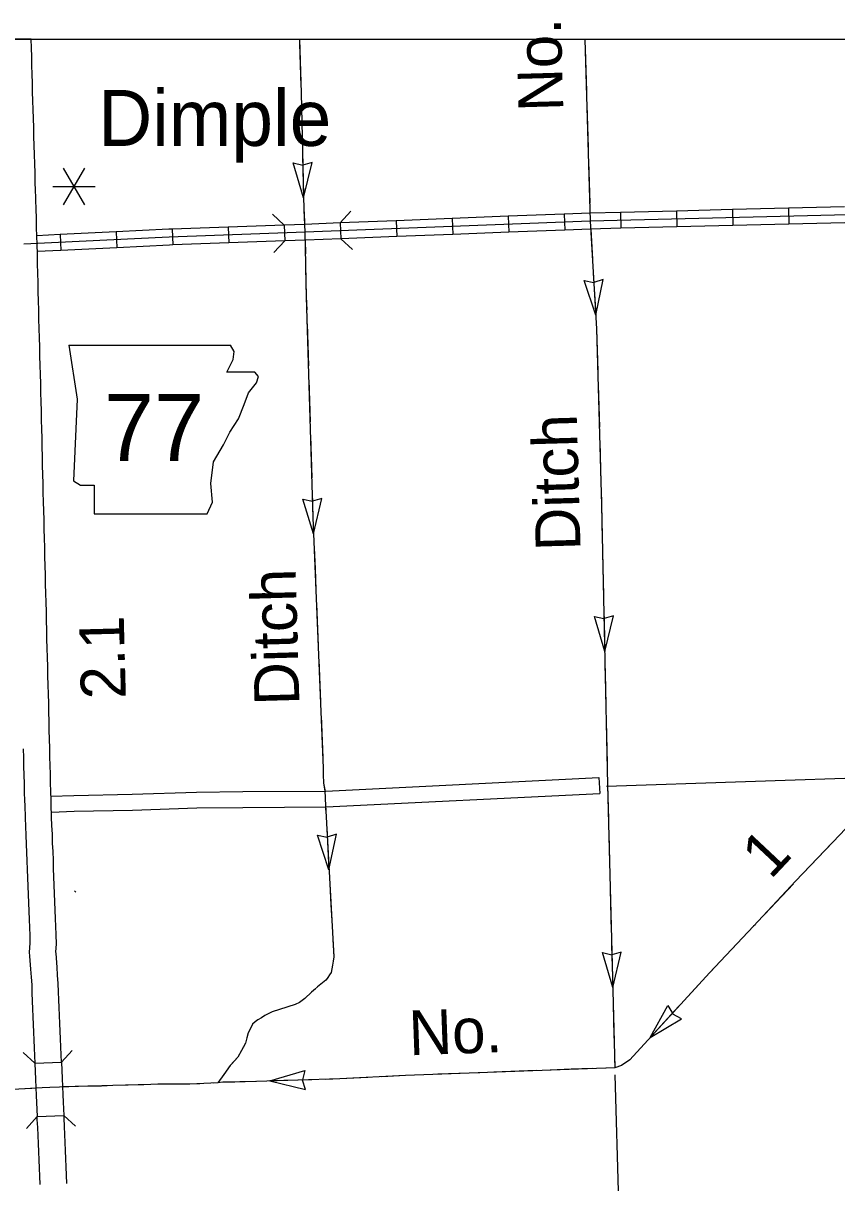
# Model space of a CAD drawing. Extents: x -117616 to 64730, y 54117 to 789866.
# Drawn here: x 63077.4 to 63230.7, y 55099.4 to 55318 of the extents above; entities that cross this region are included whole.
import ezdxf

# ---------------------------------------------------------------- set-up
doc = ezdxf.new("R2010")
doc.units = 0
for name, color, linetype in [('10', 7, 'Continuous'), ('21', 7, 'Continuous'), ('24', 7, 'Continuous'), ('32', 7, 'Continuous'), ('35', 7, 'Continuous'), ('37', 7, 'Continuous'), ('38', 7, 'Continuous'), ('43', 7, 'Continuous'), ('46', 7, 'Continuous'), ('48', 7, 'Continuous'), ('5', 7, 'Continuous'), ('R_No Plot', 7, 'Continuous')]:
    doc.layers.add(name, color=color, linetype=linetype)

msp = doc.modelspace()

# ---------------------------------------------------------------- linework, layer by layer
at = {"layer": '10'}
for p, q in [((63078.91, 55314.94), (63073.89, 55314.94)), ((63079, 55313.33), (63078.91, 55314.94)), ((63079.05, 55311.64), (63079, 55313.33)), ((63079.08, 55309.98), (63079.05, 55311.64)), ((63079.13, 55308.34), (63079.08, 55309.98)), ((63079.17, 55306.68), (63079.13, 55308.34)), ((63079.22, 55305.02), (63079.17, 55306.68)), ((63079.27, 55303.36), (63079.22, 55305.02)), ((63079.32, 55301.69), (63079.27, 55303.36)), ((63079.38, 55300.02), (63079.32, 55301.69)), ((63079.43, 55298.32), (63079.38, 55300.02)), ((63079.47, 55296.61), (63079.43, 55298.32)), ((63079.51, 55294.91), (63079.47, 55296.61)), ((63079.56, 55293.21), (63079.51, 55294.91)), ((63079.61, 55291.5), (63079.56, 55293.21)), ((63079.67, 55289.79), (63079.61, 55291.5)), ((63079.72, 55288.07), (63079.67, 55289.79)), ((63079.77, 55286.36), (63079.72, 55288.07)), ((63079.8, 55285.23), (63079.77, 55286.36)), ((63079.82, 55284.66), (63079.8, 55285.23)), ((63079.87, 55282.96), (63079.82, 55284.66)), ((63079.93, 55281.24), (63079.87, 55282.96)), ((63079.97, 55279.52), (63079.93, 55281.24)), ((63080.01, 55277.8), (63079.97, 55279.52)), ((63080.05, 55276.38), (63080.01, 55277.8)), ((63080.11, 55274.35), (63080.05, 55276.38)), ((63080.15, 55272.62), (63080.11, 55274.35)), ((63080.2, 55270.88), (63080.15, 55272.62)), ((63080.24, 55269.13), (63080.2, 55270.88)), ((63080.28, 55267.38), (63080.24, 55269.13)), ((63080.32, 55265.64), (63080.28, 55267.38)), ((63080.36, 55263.91), (63080.32, 55265.64)), ((63080.41, 55262.17), (63080.36, 55263.91)), ((63080.46, 55260.43), (63080.41, 55262.17)), ((63080.5, 55258.7), (63080.46, 55260.43)), ((63080.55, 55256.98), (63080.5, 55258.7)), ((63080.6, 55255.25), (63080.55, 55256.98)), ((63080.65, 55253.52), (63080.6, 55255.25)), ((63080.69, 55251.8), (63080.65, 55253.52)), ((63080.74, 55250.07), (63080.69, 55251.8)), ((63080.79, 55248.35), (63080.74, 55250.07)), ((63080.83, 55246.63), (63080.79, 55248.35)), ((63080.87, 55244.91), (63080.83, 55246.63)), ((63080.9, 55243.2), (63080.87, 55244.91)), ((63080.95, 55241.49), (63080.9, 55243.2)), ((63080.99, 55239.78), (63080.95, 55241.49)), ((63081.03, 55238.07), (63080.99, 55239.78)), ((63081.07, 55236.36), (63081.03, 55238.07)), ((63081.1, 55234.65), (63081.07, 55236.36)), ((63081.14, 55232.95), (63081.1, 55234.65)), ((63081.19, 55231.24), (63081.14, 55232.95)), ((63081.23, 55229.52), (63081.19, 55231.24)), ((63081.28, 55227.8), (63081.23, 55229.52)), ((63081.32, 55226.08), (63081.28, 55227.8)), ((63081.37, 55224.36), (63081.32, 55226.08)), ((63081.41, 55222.63), (63081.37, 55224.36)), ((63081.45, 55220.9), (63081.41, 55222.63)), ((63081.5, 55219.17), (63081.45, 55220.9)), ((63081.54, 55217.44), (63081.5, 55219.17)), ((63081.58, 55215.71), (63081.54, 55217.44)), ((63081.62, 55213.99), (63081.58, 55215.71)), ((63081.67, 55212.27), (63081.62, 55213.99)), ((63081.72, 55210.54), (63081.67, 55212.27)), ((63081.76, 55208.81), (63081.72, 55210.54)), ((63081.8, 55207.08), (63081.76, 55208.81)), ((63081.84, 55205.36), (63081.8, 55207.08)), ((63081.88, 55203.64), (63081.84, 55205.36)), ((63081.92, 55201.91), (63081.88, 55203.64)), ((63081.97, 55200.19), (63081.92, 55201.91)), ((63082.01, 55198.46), (63081.97, 55200.19)), ((63082.06, 55196.73), (63082.01, 55198.46)), ((63082.11, 55195), (63082.06, 55196.73)), ((63082.15, 55193.28), (63082.11, 55195)), ((63082.2, 55191.56), (63082.15, 55193.28)), ((63082.24, 55189.84), (63082.2, 55191.56)), ((63082.27, 55188.12), (63082.24, 55189.84)), ((63082.31, 55186.42), (63082.27, 55188.12)), ((63082.35, 55184.74), (63082.31, 55186.42)), ((63082.4, 55183.05), (63082.35, 55184.74)), ((63082.44, 55181.37), (63082.4, 55183.05)), ((63077.44, 55181.25), (63077.47, 55179.58)), ((63077.47, 55179.58), (63077.52, 55177.93)), ((63082.47, 55179.7), (63082.44, 55181.37)), ((63082.51, 55178.06), (63082.47, 55179.7)), ((63077.52, 55177.93), (63077.56, 55176.29)), ((63082.56, 55176.43), (63082.51, 55178.06)), ((63077.56, 55176.29), (63077.61, 55174.68)), ((63082.6, 55174.8), (63082.56, 55176.43)), ((63077.61, 55174.68), (63077.64, 55173.07)), ((63077.64, 55173.07), (63077.69, 55171.43)), ((63082.64, 55173.19), (63082.6, 55174.8)), ((63082.68, 55171.62), (63082.64, 55173.19)), ((63077.69, 55171.43), (63077.73, 55170.59)), ((63082.72, 55170.77), (63082.68, 55171.62)), ((63082.79, 55168.38), (63082.72, 55170.77)), ((63077.73, 55170.59), (63077.79, 55168.2)), ((63077.79, 55168.2), (63077.87, 55166.59)), ((63077.87, 55166.59), (63077.93, 55164.97)), ((63082.86, 55166.8), (63082.79, 55168.38)), ((63082.93, 55165.15), (63082.86, 55166.8)), ((63077.93, 55164.97), (63077.99, 55163.27)), ((63082.98, 55163.47), (63082.93, 55165.15)), ((63077.99, 55163.27), (63078.06, 55161.69)), ((63083.06, 55161.91), (63082.98, 55163.47)), ((63083.12, 55160.27), (63083.06, 55161.91)), ((63078.06, 55161.69), (63078.12, 55160.09)), ((63078.12, 55160.09), (63078.18, 55158.49)), ((63083.18, 55158.67), (63083.12, 55160.27)), ((63078.18, 55158.49), (63078.24, 55156.89)), ((63083.24, 55157.08), (63083.18, 55158.67)), ((63078.24, 55156.89), (63078.3, 55155.33)), ((63083.3, 55155.51), (63083.24, 55157.08)), ((63083.35, 55153.94), (63083.3, 55155.51)), ((63078.3, 55155.33), (63078.35, 55153.76)), ((63078.35, 55153.76), (63078.42, 55152.19)), ((63083.41, 55152.4), (63083.35, 55153.94)), ((63078.42, 55152.19), (63078.48, 55150.63)), ((63083.48, 55150.84), (63083.41, 55152.4)), ((63078.48, 55150.63), (63078.55, 55149.09)), ((63078.55, 55149.09), (63078.6, 55147.55)), ((63083.54, 55149.28), (63083.48, 55150.84)), ((63083.6, 55147.75), (63083.54, 55149.28)), ((63078.6, 55147.55), (63078.67, 55146.04)), ((63083.67, 55146.24), (63083.6, 55147.75)), ((63078.72, 55144.59), (63078.56, 55142.9)), ((63078.67, 55146.04), (63078.72, 55144.59)), ((63083.59, 55142.95), (63083.73, 55144.44)), ((63083.73, 55144.44), (63083.67, 55146.24)), ((63078.56, 55142.9), (63078.64, 55142.16)), ((63083.62, 55142.63), (63083.59, 55142.95)), ((63083.82, 55140.07), (63083.62, 55142.63)), ((63078.64, 55142.16), (63078.83, 55139.71)), ((63083.92, 55138.56), (63083.82, 55140.07)), ((63078.83, 55139.71), (63078.94, 55138.21)), ((63078.94, 55138.21), (63079.04, 55136.77)), ((63084.03, 55137.02), (63083.92, 55138.56)), ((63079.04, 55136.77), (63079.08, 55135.25)), ((63084.08, 55135.43), (63084.03, 55137.02)), ((63079.08, 55135.25), (63079.15, 55133.68)), ((63079.15, 55133.68), (63079.22, 55132.23)), ((63084.14, 55133.91), (63084.08, 55135.43)), ((63084.21, 55132.46), (63084.14, 55133.91)), ((63079.22, 55132.23), (63079.28, 55130.75)), ((63084.28, 55130.96), (63084.21, 55132.46)), ((63079.28, 55130.75), (63079.34, 55129.28)), ((63079.34, 55129.28), (63079.41, 55127.82)), ((63084.34, 55129.49), (63084.28, 55130.96)), ((63084.4, 55128.04), (63084.34, 55129.49)), ((63079.41, 55127.82), (63079.47, 55126.35)), ((63084.47, 55126.56), (63084.4, 55128.04)), ((63079.47, 55126.35), (63079.53, 55124.87)), ((63079.53, 55124.87), (63079.59, 55123.36)), ((63084.53, 55125.08), (63084.47, 55126.56)), ((63084.59, 55123.57), (63084.53, 55125.08)), ((63079.59, 55123.36), (63079.66, 55121.97)), ((63084.65, 55122.19), (63084.59, 55123.57)), ((63079.66, 55121.97), (63084.65, 55122.19))]:
    msp.add_line(p, q, dxfattribs=at)
for points in [[(63079.66, 55121.97), (63079.78, 55118.92), (63079.83, 55117.4), (63079.9, 55115.9), (63080.08, 55111.91)], [(63084.65, 55122.19), (63084.78, 55119.1), (63084.83, 55117.59), (63084.89, 55116.11), (63084.96, 55114.62), (63085.07, 55112.14)], [(63080.08, 55111.91), (63085.07, 55112.14), (63085.1, 55111.61), (63085.17, 55110.08), (63085.23, 55108.55), (63085.29, 55107.03), (63085.35, 55105.51), (63085.42, 55103.98), (63085.49, 55102.44), (63085.55, 55100.89), (63085.62, 55099.33)], [(63080.63, 55099.12), (63080.56, 55100.67), (63080.49, 55102.23), (63080.43, 55103.76), (63080.36, 55105.3), (63080.3, 55106.83), (63080.24, 55108.35), (63080.17, 55109.87), (63080.1, 55111.38), (63080.08, 55111.91)]]:
    msp.add_lwpolyline(points, dxfattribs=at)
at = {"layer": '21'}
for p, q in [((63086.05, 55257.3), (63087.58, 55247.15)), ((63117.18, 55256.11), (63116.48, 55257.28)), ((63117.01, 55254.59), (63117.18, 55256.11)), ((63115.83, 55252.22), (63117.01, 55254.59)), ((63121.07, 55252.22), (63115.83, 55252.22)), ((63121.75, 55251.37), (63121.07, 55252.22)), ((63119.89, 55248.33), (63121.41, 55250.19)), ((63121.41, 55250.19), (63121.75, 55251.37)), ((63087.58, 55247.15), (63086.9, 55231.75)), ((63119.04, 55246.13), (63119.89, 55248.33)), ((63118.03, 55243.42), (63119.04, 55246.13)), ((63116.34, 55240.89), (63118.03, 55243.42)), ((63115.15, 55238.52), (63116.34, 55240.89)), ((63113.29, 55235.3), (63115.15, 55238.52)), ((63112.78, 55231.24), (63113.29, 55235.3)), ((63086.9, 55231.75), (63088.25, 55230.9)), ((63088.25, 55230.9), (63090.79, 55230.9)), ((63090.79, 55230.9), (63090.79, 55225.49)), ((63113.12, 55227.69), (63112.78, 55231.24)), ((63112.11, 55225.49), (63113.12, 55227.69)), ((63090.79, 55225.49), (63112.11, 55225.49))]:
    msp.add_line(p, q, dxfattribs=at)
msp.add_lwpolyline([(63086.05, 55257.3), (63116.48, 55257.28)], dxfattribs=at)
at = {"layer": '32'}
for p, q in [((63189.94, 55282.33), (63190.01, 55279.33)), ((63200.5, 55282.58), (63200.57, 55279.58)), ((63211.05, 55282.84), (63211.13, 55279.84)), ((63221.61, 55283.09), (63221.68, 55280.09)), ((63126.61, 55279.94), (63126.72, 55276.94)), ((63137.16, 55280.34), (63137.27, 55277.34)), ((63147.71, 55280.75), (63147.83, 55277.75)), ((63158.26, 55281.17), (63158.38, 55278.17)), ((63168.81, 55281.58), (63168.93, 55278.59)), ((63179.36, 55282), (63179.48, 55279)), ((63084.39, 55278.15), (63084.53, 55275.15)), ((63094.93, 55278.67), (63095.08, 55275.67)), ((63105.5, 55279.18), (63105.61, 55276.18)), ((63116.06, 55279.56), (63116.16, 55276.56))]:
    msp.add_line(p, q, dxfattribs=at)
for points in [[(63316.65, 55284.1), (63306.85, 55283.83), (63289.12, 55283.22), (63184.28, 55280.69), (63130.56, 55278.58), (63104.94, 55277.66), (63077.55, 55276.31)], [(63189.94, 55282.33), (63184.23, 55282.19), (63179.36, 55282)], [(63200.5, 55282.58), (63189.94, 55282.33)], [(63211.05, 55282.84), (63200.5, 55282.58)], [(63221.61, 55283.09), (63211.05, 55282.84)], [(63232.17, 55283.35), (63221.61, 55283.09)], [(63126.61, 55279.94), (63116.06, 55279.56)], [(63137.16, 55280.34), (63130.51, 55280.07), (63126.61, 55279.94)], [(63147.71, 55280.75), (63137.16, 55280.34)], [(63158.26, 55281.17), (63147.71, 55280.75)], [(63168.81, 55281.58), (63158.26, 55281.17)], [(63179.36, 55282), (63168.81, 55281.58)], [(63221.68, 55280.09), (63211.13, 55279.84)], [(63232.24, 55280.35), (63221.68, 55280.09)], [(63084.39, 55278.15), (63080.01, 55277.93)], [(63094.93, 55278.67), (63084.39, 55278.15)], [(63105.5, 55279.18), (63104.87, 55279.16), (63094.93, 55278.67)], [(63116.06, 55279.56), (63105.5, 55279.18)], [(63147.83, 55277.75), (63137.27, 55277.34)], [(63158.38, 55278.17), (63147.83, 55277.75)], [(63168.93, 55278.59), (63158.38, 55278.17)], [(63179.48, 55279), (63168.93, 55278.59)], [(63190.01, 55279.33), (63184.33, 55279.19), (63179.48, 55279)], [(63200.57, 55279.58), (63190.01, 55279.33)], [(63211.13, 55279.84), (63200.57, 55279.58)], [(63095.08, 55275.67), (63084.53, 55275.15)], [(63105.61, 55276.18), (63105, 55276.16), (63095.08, 55275.67)], [(63116.16, 55276.56), (63105.61, 55276.18)], [(63126.72, 55276.94), (63116.16, 55276.56)], [(63137.27, 55277.34), (63130.62, 55277.08), (63126.72, 55276.94)], [(63084.53, 55275.15), (63080.09, 55274.93)]]:
    msp.add_lwpolyline(points, dxfattribs=at)
at = {"layer": '35'}
msp.add_lwpolyline([(63087.08, 55154.48), (63087.35, 55154.2)], dxfattribs=at)
at = {"layer": '37'}
for points in [[(63079.66, 55121.98), (63077.44, 55124)], [(63086.68, 55124.4), (63084.65, 55122.19)], [(63078.06, 55109.69), (63080.08, 55111.91)], [(63085.07, 55112.14), (63087.29, 55110.12)]]:
    msp.add_lwpolyline(points, dxfattribs=at)
at = {"layer": '38'}
for points in [[(63137.16, 55280.34), (63139.19, 55282.54)], [(63124.41, 55281.98), (63126.61, 55279.94)], [(63126.72, 55276.94), (63124.67, 55274.74)], [(63139.48, 55275.3), (63137.27, 55277.34)]]:
    msp.add_lwpolyline(points, dxfattribs=at)
at = {"layer": '43'}
for p, q in [((63130.27, 55285.06), (63128.33, 55291.64)), ((63128.33, 55291.64), (63130.11, 55291.21)), ((63131.88, 55291.73), (63130.13, 55291.21)), ((63130.27, 55285.06), (63131.88, 55291.73)), ((63185.29, 55262.94), (63183.14, 55269.46)), ((63183.14, 55269.46), (63184.93, 55269.08)), ((63186.69, 55269.66), (63184.95, 55269.09)), ((63185.29, 55262.94), (63186.69, 55269.66)), ((63132.12, 55221.73), (63130.14, 55228.3)), ((63130.14, 55228.3), (63131.92, 55227.88)), ((63133.7, 55228.41), (63131.95, 55227.88)), ((63132.12, 55221.73), (63133.7, 55228.41)), ((63186.99, 55199.6), (63185.07, 55206.19)), ((63185.07, 55206.19), (63186.85, 55205.76)), ((63188.62, 55206.27), (63186.87, 55205.76)), ((63186.99, 55199.6), (63188.62, 55206.27)), ((63135.04, 55158.45), (63132.91, 55164.97)), ((63132.91, 55164.97), (63134.7, 55164.59)), ((63136.46, 55165.16), (63134.72, 55164.6)), ((63135.04, 55158.45), (63136.46, 55165.16)), ((63188.5, 55136.26), (63186.55, 55142.84)), ((63186.55, 55142.84), (63188.33, 55142.42)), ((63190.11, 55142.93), (63188.36, 55142.42)), ((63188.5, 55136.26), (63190.11, 55142.93)), ((63195.56, 55126.81), (63198.86, 55132.83)), ((63198.86, 55132.83), (63199.81, 55131.27)), ((63195.56, 55126.81), (63201.43, 55130.37)), ((63201.43, 55130.37), (63199.83, 55131.25)), ((63123.93, 55118.63), (63130.5, 55120.6)), ((63130.5, 55120.6), (63130.08, 55118.82)), ((63123.93, 55118.63), (63130.61, 55117.05)), ((63130.61, 55117.05), (63130.08, 55118.8))]:
    msp.add_line(p, q, dxfattribs=at)
for points in [[(63129.47, 55314.94), (63129.78, 55304.8), (63130.32, 55282.83), (63130.51, 55278.57), (63130.77, 55266.4), (63132.03, 55224.82), (63133.95, 55177.61), (63133.93, 55176.42), (63134.03, 55174.73), (63134.24, 55173.52), (63134.32, 55171.78), (63135.94, 55142.01), (63135.86, 55141.2), (63135.69, 55140.49), (63135.45, 55139.1), (63135.17, 55138.62), (63134.83, 55138.11), (63134.46, 55137.63), (63133.8, 55137.16), (63132.91, 55136.36), (63131.78, 55135.37), (63130.51, 55134.16), (63129.52, 55133.41), (63128.65, 55133.03), (63124.37, 55131.69), (63122.98, 55130.98), (63122.33, 55130.54), (63121.65, 55130.13), (63121.16, 55129.75), (63120.64, 55129.33), (63120.19, 55128.38), (63119.81, 55127.68), (63119.54, 55126.77), (63119.35, 55125.74), (63118.57, 55124.37), (63117.85, 55123.11), (63116.46, 55121.53), (63115.25, 55119.85), (63114.08, 55118.27)], [(63183.23, 55314.94), (63184.28, 55280.69), (63185.44, 55260.38), (63186.41, 55227.2), (63187.52, 55174.42), (63188.89, 55121.13)], [(63129.49, 55314.09), (63129.74, 55306.17)], [(63183.28, 55313.05), (63183.53, 55305.14)], [(63183.61, 55302.5), (63183.85, 55294.58)], [(63130.07, 55292.98), (63130.27, 55285.06)], [(63183.93, 55291.94), (63184.18, 55284.03)], [(63130.34, 55282.42), (63130.44, 55280.07)], [(63184.36, 55279.19), (63184.69, 55273.48)], [(63130.54, 55277.07), (63130.6, 55274.5)], [(63130.65, 55271.86), (63130.77, 55266.4), (63130.85, 55263.95)], [(63184.84, 55270.85), (63185.29, 55262.94)], [(63130.93, 55261.31), (63131.17, 55253.39)], [(63185.44, 55260.3), (63185.56, 55256.34)], [(63185.56, 55256.34), (63185.67, 55252.39)], [(63131.25, 55250.75), (63131.48, 55242.84)], [(63185.75, 55249.75), (63185.98, 55241.83)], [(63131.56, 55240.2), (63131.8, 55232.28)], [(63186.06, 55239.19), (63186.29, 55231.27)], [(63131.88, 55229.64), (63132.03, 55224.82), (63132.15, 55221.73)], [(63186.37, 55228.64), (63186.41, 55227.2), (63186.54, 55220.72)], [(63132.26, 55219.09), (63132.42, 55215.13)], [(63186.6, 55218.08), (63186.77, 55210.16)], [(63132.42, 55215.13), (63132.58, 55211.18)], [(63132.69, 55208.54), (63133.01, 55200.62)], [(63186.82, 55207.52), (63186.99, 55199.6)], [(63133.12, 55197.99), (63133.44, 55190.07)], [(63187.04, 55196.96), (63187.13, 55193)], [(63187.13, 55193), (63187.21, 55189.04)], [(63133.55, 55187.44), (63133.87, 55179.52)], [(63187.26, 55186.41), (63187.43, 55178.49)], [(63133.94, 55176.88), (63133.93, 55176.42), (63134.03, 55174.73), (63134.28, 55173.28)], [(63187.49, 55175.85), (63187.52, 55174.42), (63187.68, 55167.93)], [(63236.08, 55170.03), (63229.97, 55163.64), (63222.96, 55156.28), (63215.05, 55147.8), (63206.75, 55139.03), (63191.74, 55122.64), (63190.16, 55121.57), (63188.89, 55121.13), (63149.49, 55119.69), (63137.09, 55119.01), (63121.36, 55118.56), (63115.08, 55118.38), (63114.08, 55118.27), (63108.82, 55118.02), (63103.84, 55118.04), (63094.31, 55117.76), (63092.19, 55117.68), (63089.68, 55117.68)], [(63236.08, 55170.03), (63229.97, 55163.64), (63222.96, 55156.28), (63215.05, 55147.8), (63206.75, 55139.03), (63191.74, 55122.64), (63190.16, 55121.57), (63188.89, 55121.13), (63149.49, 55119.69), (63137.09, 55119.01), (63121.36, 55118.56), (63115.08, 55118.38), (63114.08, 55118.27), (63108.82, 55118.02), (63103.84, 55118.04), (63094.31, 55117.76), (63092.19, 55117.68), (63089.68, 55117.68)], [(63134.4, 55170.28), (63134.47, 55168.99)], [(63134.61, 55166.35), (63135.04, 55158.45)], [(63187.75, 55165.29), (63187.96, 55157.37)], [(63229.8, 55163.46), (63227.07, 55160.6)], [(63227.07, 55160.6), (63224.34, 55157.73)], [(63135.19, 55155.81), (63135.41, 55151.86)], [(63222.53, 55155.81), (63217.12, 55150.02)], [(63188.02, 55154.73), (63188.23, 55146.82)], [(63135.41, 55151.86), (63135.62, 55147.9)], [(63215.32, 55148.09), (63215.05, 55147.8), (63209.88, 55142.33)], [(63135.77, 55145.27), (63135.94, 55142.01), (63135.86, 55141.2), (63135.69, 55140.49), (63135.45, 55139.1), (63135.17, 55138.62), (63134.83, 55138.11), (63134.5, 55137.69)], [(63188.3, 55144.18), (63188.5, 55136.26)], [(63208.07, 55140.42), (63206.75, 55139.03), (63202.69, 55134.6)], [(63132.49, 55135.99), (63131.78, 55135.37), (63130.51, 55134.16), (63129.52, 55133.41), (63128.65, 55133.03), (63125.75, 55132.13)], [(63188.57, 55133.62), (63188.67, 55129.66)], [(63200.91, 55132.65), (63195.56, 55126.81)], [(63123.31, 55131.15), (63122.98, 55130.98), (63122.33, 55130.54), (63121.65, 55130.13), (63121.16, 55129.75), (63120.64, 55129.33), (63120.19, 55128.38), (63119.81, 55127.68), (63119.54, 55126.77), (63119.35, 55125.74), (63118.93, 55125.01)], [(63188.67, 55129.66), (63188.77, 55125.7)], [(63193.78, 55124.86), (63191.74, 55122.64), (63190.16, 55121.57), (63188.89, 55121.13), (63187.24, 55121.07)], [(63117.55, 55122.77), (63116.46, 55121.53), (63115.25, 55119.85), (63114.08, 55118.27)], [(63188.84, 55123.07), (63188.89, 55121.13)], [(63174.05, 55120.59), (63166.13, 55120.3)], [(63180.64, 55120.83), (63176.69, 55120.68)], [(63184.6, 55120.97), (63180.64, 55120.83)], [(63117.33, 55118.44), (63115.08, 55118.38), (63114.08, 55118.27), (63113.38, 55118.24)], [(63121.29, 55118.56), (63117.33, 55118.44)], [(63131.84, 55118.86), (63123.93, 55118.63)], [(63142.39, 55119.3), (63137.09, 55119.01), (63134.48, 55118.94)], [(63152.94, 55119.81), (63149.49, 55119.69), (63145.03, 55119.44)], [(63163.49, 55120.2), (63155.58, 55119.91)], [(63089.68, 55117.68), (63082.47, 55117.42), (63080.99, 55117.34), (63076.62, 55117.1), (63069.39, 55116.94), (63067.43, 55116.75), (63065.81, 55116.56), (63064.77, 55116.34), (63064.23, 55116.15), (63063.75, 55115.8), (63063.34, 55115.23), (63062.53, 55113.89), (63056.78, 55103.99), (63056.27, 55102.46), (63055.99, 55101.49), (63055.89, 55100), (63056.18, 55098.62)], [(63089.68, 55117.68), (63082.47, 55117.42), (63080.99, 55117.34), (63076.62, 55117.1), (63069.39, 55116.94), (63067.43, 55116.75), (63065.81, 55116.56), (63064.77, 55116.34), (63064.23, 55116.15), (63063.75, 55115.8), (63063.34, 55115.23), (63062.53, 55113.89), (63056.78, 55103.99), (63056.27, 55102.46), (63055.99, 55101.49), (63055.89, 55100), (63056.18, 55098.62)], [(63079.08, 55117.23), (63076.62, 55117.1), (63071.16, 55116.98)], [(63089.63, 55117.68), (63084.83, 55117.5)], [(63100.19, 55117.93), (63094.31, 55117.76), (63092.27, 55117.69)], [(63110.74, 55118.11), (63108.82, 55118.02), (63103.84, 55118.04), (63102.82, 55118.01)]]:
    msp.add_lwpolyline(points, dxfattribs=at)
at = {"layer": '46'}
for points in [[(63082.65, 55172.28), (63086.96, 55172.46), (63097.94, 55172.68), (63110.07, 55173.08), (63118.81, 55173.19), (63134.45, 55173.28), (63185.9, 55175.84), (63186.05, 55172.84)], [(63082.76, 55169.28), (63087.05, 55169.46), (63098.02, 55169.68), (63110.13, 55170.09), (63118.84, 55170.19), (63134.54, 55170.28), (63186.05, 55172.84)]]:
    msp.add_lwpolyline(points, dxfattribs=at)
at = {"layer": '48'}
for p, q in [((63089, 55290.65), (63085, 55283.72)), ((63085, 55290.65), (63089, 55283.72)), ((63083, 55287.19), (63091, 55287.19))]:
    msp.add_line(p, q, dxfattribs=at)
at = {"layer": '5'}
for points in [[(63239.67, 55175.88), (63187.33, 55174.12)], [(63190.37, 55071.57), (63188.94, 55119.81)]]:
    msp.add_lwpolyline(points, dxfattribs=at)
at = {"layer": 'R_No Plot'}
msp.add_lwpolyline([(62347.42, 55314.94), (63854.85, 55314.94), (63854.85, 54389.3), (62347.42, 54389.3)], close=True, dxfattribs=at)

# ---------------------------------------------------------------- texts
at = {"layer": '21'}
msp.add_text('77', height=12.672, dxfattribs=at).set_placement((63092.66, 55235.45))
at = {"layer": '24'}
msp.add_text('Dimple', height=10.56, dxfattribs=at).set_placement((63091.55, 55294.85))
at = {"layer": '43'}
for s, height, rotation, p in [('No.', 8.448, 91.6429, (63179.21, 55301.43)), ('Ditch', 8.448, 91.6737, (63182.46, 55218.65)), ('Ditch', 8.448, 91.6737, (63129.49, 55189.53)), ('1', 8.45, 46.82, (63218.23, 55156.45)), ('No.', 8.448, 2.0998, (63150.22, 55123.46))]:
    msp.add_text(s, height=height, rotation=rotation, dxfattribs=at).set_placement(p)
at = {"layer": '48'}
msp.add_text('2.1', height=8.448, rotation=91.5083, dxfattribs=at).set_placement((63096.79, 55190.69))

doc.saveas('drawing.dxf')
